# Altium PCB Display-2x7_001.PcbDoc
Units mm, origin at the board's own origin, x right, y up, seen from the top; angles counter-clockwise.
Board outline 37.38 x 73.8 mm, 2 copper layers (Top Layer, Bottom Layer), stack 1.571 mm thick; 20 components, 35 nets, 104 pads, 23 vias.
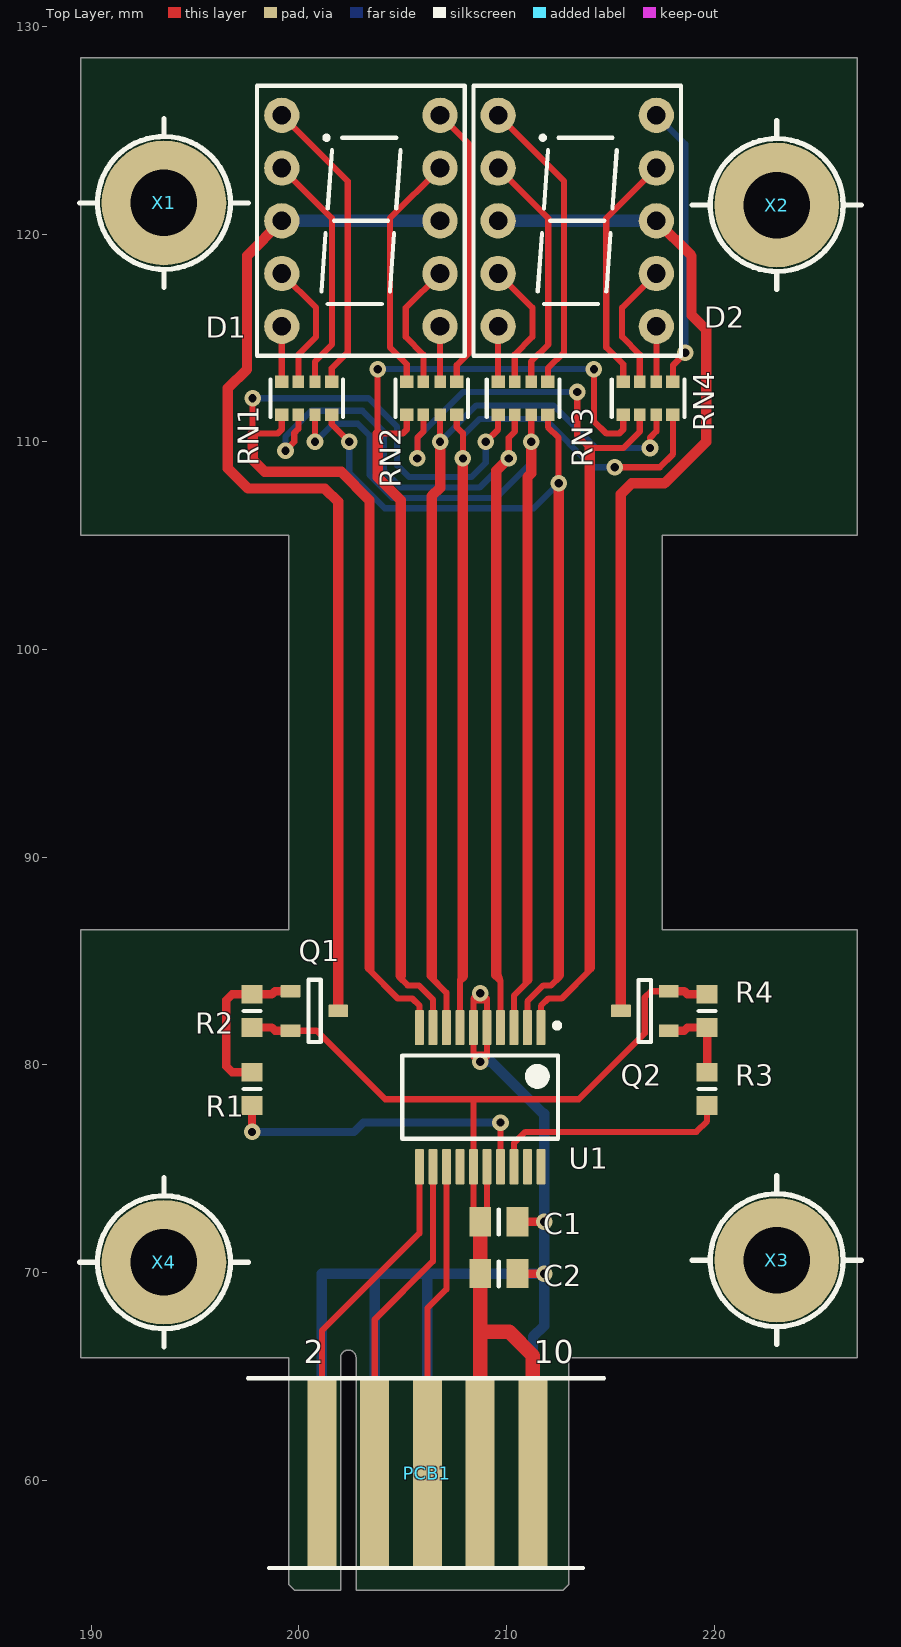
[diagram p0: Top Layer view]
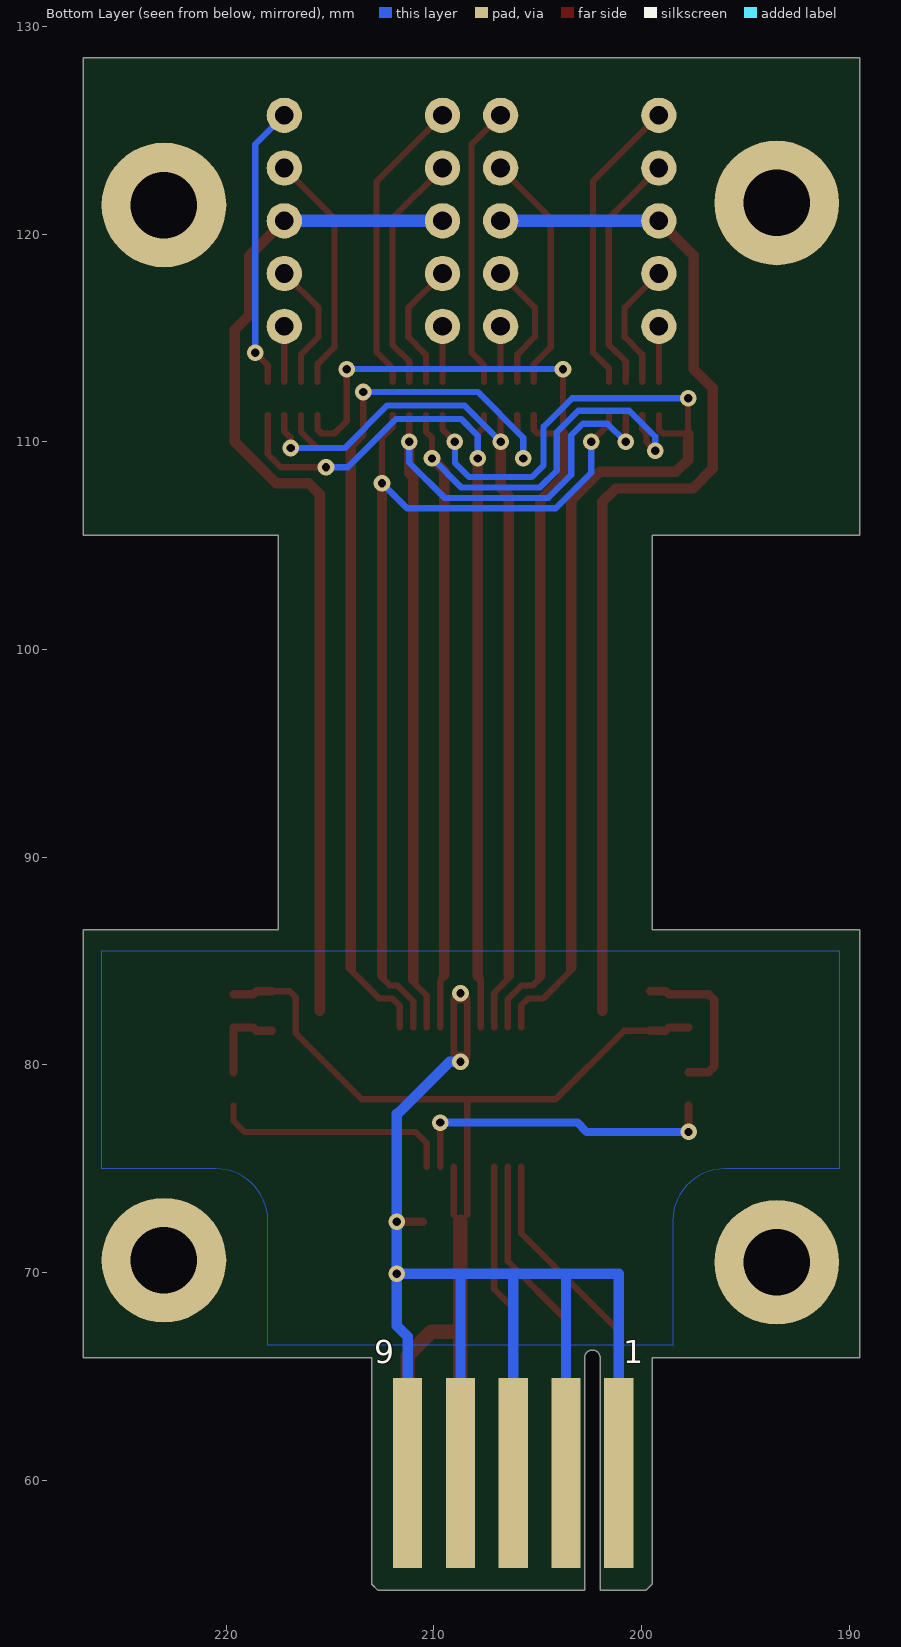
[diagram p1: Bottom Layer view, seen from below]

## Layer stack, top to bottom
Top Solder: solder mask 0.0102, Solder Resist, Dk 3.5
Top Layer: signal copper 0.0356
Flexpart Dielectric: dielectric 0.1, FR-4, Dk 4.2
Core Dielectric: dielectric 1.4, FR-4, Dk 4.2
Bottom Layer: signal copper 0.0356
Bottom Solder: solder mask 0.0102, Solder Resist, Dk 3.5

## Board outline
199.5,55 199.5,65.9 189.5,65.9 189.5,86.5 199.5,86.5 199.5,105.5 189.5,105.5 189.5,128.5 226.88,128.5 226.88,105.5 217.5,105.5 217.5,86.5 226.88,86.5 226.88,65.9 213,65.9 213,55 212.7,54.7 202.75,54.7 202.75,65.9 ccw(c202.375,65.9) 202,65.9 202,54.7 199.8,54.7
board region LED: 199.5,104.5 199.5,105.5 189.5,105.5 189.5,128.5 226.88,128.5 226.88,105.5 217.5,105.5 217.5,104.5
board region IC: 217.5,87.5 217.5,86.5 226.88,86.5 226.88,65.9 213,65.9 213,55 212.7,54.7 202.75,54.7 202.757,65.9 202.728,66.046 202.645,66.17 202.521,66.253 202.375,66.282 202.229,66.253 202.105,66.17 202.022,66.046 201.993,65.9 202,65.9 202,54.7 199.8,54.7 199.5,55 199.5,65.9 189.5,65.9 189.5,86.5 199.5,86.5 199.5,87.5
board region Flex: 217.5,104.5 217.5,87.5 199.5,87.5 199.5,104.5

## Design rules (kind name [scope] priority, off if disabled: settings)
Clearance [All] p1: gap=0.2
MinimumSolderMaskSliver [All] p1: minsoldermaskwidth=0.2
PolygonConnect [All] p1: connectstyle=Relief reliefconductorwidth=0.254 reliefentries=4 polygonreliefangle="90 Angle" airgapwidth=0.254
RoutingVias [All] p1: holewidth=0.5 width=1.27 viastyle="Through Hole" minholewidth=0.4 minwidth=0.8 maxholewidth=0.7 maxwidth=1
SolderMaskExpansion [All] p1: expansion=0.102
Width [All] p1: maxlimit=1 minlimit=0.254 preferedwidth=0.3 minimp=50.000000 maximp=50.000000 favimp=50.000000
28 further rules are at their usual default settings.

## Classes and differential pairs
component class Display-2x7: C1 C2 PCB1 Q1 Q2 R1 R2 R3 R4 U1 X3 X4

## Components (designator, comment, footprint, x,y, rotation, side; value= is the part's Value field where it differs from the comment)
C1 "100n, X7R, 50V" CAPC2012X135N 209.625,72.45 r180 top
C2 "100n, X7R, 50V" CAPC2012X135N 209.625,69.95 r180 top
D1 "SA39-11PBWA" LED_KINGBRIGHT_SA39-11PBWA 202.983,120.64 r180 top
D2 "SA39-11PBWA" LED_KINGBRIGHT_SA39-11PBWA 213.397,120.64 r180 top
PCB1 "PCB_KS_3M_3358" KS_3M_3358 206.185,60.35 r180 top
Q1 "BC856B" SOT95P230X110-3N 200.743,82.6 r0 top
Q2 "BC856B" SOT95P230X110-3N 216.65,82.6 r180 top
R1 "3k3, 5%" RESC1608X55N 197.743,78.85 r270 top
R2 "3k3, 5%" RESC1608X55N 197.743,82.6 r90 top
R3 "3k3, 5%" RESC1608X55N 219.65,78.85 r270 top
R4 "3k3, 5%" RESC1608X55N 219.65,82.6 r270 top
RN1 "4x100R" RESCAV80P160X320X55-8N 200.373,112.093 r90 top
RN2 "4x100R" RESCAV80P160X320X55-8N 206.393,112.093 r90 top
RN3 "4x100R" RESCAV80P160X320X55-8N 210.787,112.093 r90 top
RN4 "4x100R" RESCAV80P160X320X55-8N 216.807,112.093 r90 top
U1 "THC_IC_16C770-IL20" SOP65P780X200-20N 208.725,78.45 r270 top
X1 "Bohrung in LP kein Bauteil" HOLE_3.2_6.0 193.5,121.5 r0 top
X2 "Bohrung in LP kein Bauteil" HOLE_3.2_6.0 223,121.4 r0 top
X3 "Bohrung in LP kein Bauteil" HOLE_3.2_6.0 223,70.6 r0 top
X4 "Bohrung in LP kein Bauteil" HOLE_3.2_6.0 193.5,70.5 r0 top

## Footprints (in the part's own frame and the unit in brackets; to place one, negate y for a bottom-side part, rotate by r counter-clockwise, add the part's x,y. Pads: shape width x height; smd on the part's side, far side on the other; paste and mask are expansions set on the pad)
CAPC2012X135N [mm] "0805"
  rect 1.05x1.4 smd: 1(-0.9,0) 2(0.9,0)
  silkscreen extent 0.01,-0.59 0.01,0.61, body extent -1.1,-0.7 1.1,0.7, height 1.35
HOLE_3.2_6.0 [mm] "Mechanik für M3 Schraube"
  round 6 hole 3.2: 1(0,0)
  silkscreen extent -4.06,-4.06 4.06,4.06
KS_3M_3358 [mm] "Direktsteckverbinder 3000 Serie 10pol RM2,54"
  rect 1.4x9.14 smd far side: 1(5.08,0) 3(2.54,0) 5(0,0) 7(-2.54,0) 9(-5.08,0)
  rect 1.4x9.14 smd: 2(5.08,0) 4(2.54,0) 6(0,0) 8(-2.54,0) 10(-5.08,0)
  silkscreen extent -8.51,-4.57 8.64,4.57, body extent -7,-6.6 6.8,-5, height 0.1
LED_KINGBRIGHT_SA39-11PBWA [mm] "9.9mm (0.39inch) Kingbright Numeric Display"
  round 1.7 hole 0.9: 1(-3.81,5.08) 2(-3.81,2.54) 3(-3.81,0) 4(-3.81,-2.54) 5(-3.81,-5.08) 6(3.81,-5.08) 7(3.81,-2.54) 8(3.81,0) 9(3.81,2.54) 10(3.81,5.08)
  silkscreen extent -5,-6.5 5,6.5, body extent -5,-6.5 5,6.5, height 7
RESC1608X55N [mm] "0603"
  rect 0.9x1 smd: 1(-0.8,0) 2(0.8,0)
  silkscreen extent 0,-0.4 0,0.4, body extent -0.9,-0.5 0.9,0.5, height 0.55
RESCAV80P160X320X55-8N [mm] "WIDERSTAND ARRAY, ARV241 1206"
  rect 0.6x0.65 smd: 1(-0.8,1.2) 4(-0.8,-1.2) 5(0.8,-1.2) 8(0.8,1.2)
  rect 0.6x0.55 smd: 2(-0.8,0.4) 3(-0.8,-0.4) 6(0.8,-0.4) 7(0.8,0.4)
  silkscreen extent -0.9,-1.75 0.9,1.75, body extent -0.6,-1.6 0.6,1.6, height 0.7
SOP65P780X200-20N [mm] "SSOP20, 20-Leads, Body 7,5x5,2mm (max), Pitch 0,65mm, IPC Medium Density"
  rrect20% 1.7x0.42 smd: 1(-3.35,2.925) 2(-3.35,2.275) 3(-3.35,1.625) 4(-3.35,0.975) 5(-3.35,0.325) 6(-3.35,-0.325) 7(-3.35,-0.975) 8(-3.35,-1.625) 9(-3.35,-2.275) 10(-3.35,-2.925) 11(3.35,-2.925) 12(3.35,-2.275) 13(3.35,-1.625) 14(3.35,-0.975) 15(3.35,-0.325) 16(3.35,0.325) 17(3.35,0.975) 18(3.35,1.625) 19(3.35,2.275) 20(3.35,2.925)
  silkscreen extent -3.57,-3.75 2,3.83, body extent -2.65,-3.75 2.65,3.75, height 2
SOT95P230X110-3N [mm]
  rrect10% 0.95x0.6 smd: 1(-1.15,0.95) 3(1.15,0)
  rrect10% 0.95x0.6 smd mask+0.102: 2(-1.15,-0.95)
  silkscreen extent -0.29,-1.5 0.31,1.5, body extent -0.67,-1.5 0.68,1.5, height 1.1

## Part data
C1 C2: library part SMD_CAP_100n0_0805_X7R, "Capacitor 0805 2,0mm x 1,25mm"
D1 D2: library part THC_LED_KINGBRIGHGT_SA39-11PBWA, "9mm 7-Segment, LED, Numeric, Single Digit, Blue KINGBRIGHGT"
PCB1: "Buchsenleiste 3M Serie3000 10pol RM2.54 Card Edge"
Q1 Q2: library part SMD_PNP_BC856B_SOT23, "PNP Transistor 65V 100mA"
R1 R2 R3 R4: library part SMD_RES_003k30_0603_5%, "Resistor 0603 1,55mm x 0,85mm"
RN1 RN2 RN3 RN4: library part SMD_RES_100R00_4x0603_concave_5%, "4X100R Resistor Array 4x0603 concave 5% 63mW"
X1 X2 X3 X4: library part Hole_3.2mm_CU6.0, "Bohrung 3,2mm mit CU"

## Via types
v1: diameter 0.8, hole 0.4, Top Layer to Bottom Layer, 23 vias

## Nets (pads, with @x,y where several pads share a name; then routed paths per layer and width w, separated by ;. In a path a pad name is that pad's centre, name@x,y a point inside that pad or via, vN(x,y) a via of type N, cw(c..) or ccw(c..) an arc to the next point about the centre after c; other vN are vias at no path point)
GND: C1.1 C2.1 PCB1.1 PCB1.3 PCB1.5 PCB1.7 PCB1.9 U1.5 U1.6 | length 84.7
  Top Layer w0.3: 208.4,80.4 U1.6 208.4,83.2 208.725,83.525 209.05,83.2 U1.5 209.05,80.4
  Top Layer w0.4: C2.1 v1(211.8,69.95) ; C1.1 v1(211.8,72.45)
  Bottom Layer w0.5: PCB1.1@201.105,57.85 201.105,69.925 ; 201.105,69.95 v1(211.8,69.95) ; PCB1.3@203.645,57.85 203.645,69.925 ; PCB1.5 206.185,69.925 ; PCB1.7 208.725,69.95 ; v1(208.725,80.15) 209.25,80.15 211.8,77.6 ; PCB1.9 211.265,66.915 211.8,67.45 v1(211.8,69.95) ; 211.8,77.65 v1(211.8,69.95)
  other v1: 208.725,83.45
NetD1_1: D1.1 RN2.6 | length 2.7
  Top Layer w0.3: RN2.6 D1.1
NetD1_2: D1.2 RN2.7 | length 6.2
  Top Layer w0.3: RN2.7 205.993,114.201 205.142,115.052 205.142,116.449 D1.2
NetD1_3: D1.3 D1.8 Q1.3 | length 51.1
  Top Layer w0.5: D1.8 197.5,118.967 197.5,113.5 196.58,112.58 196.58,108.72 197.55,107.75 201.25,107.75 201.893,107.107 Q1.3
  Bottom Layer w0.6: D1.8 D1.3
NetD1_4: D1.4 RN2.8 | length 11.6
  Top Layer w0.3: RN2.8 205.193,113.731 204.38,114.544 204.38,120.767 D1.4
NetD1_5: D1.5 RN2.5 | length 13.7
  Top Layer w0.3: D1.5 208.19,124.323 208.19,114.29 207.593,113.693 RN2.5
NetD1_6: D1.6 RN1.5 | length 14.5
  Top Layer w0.3: D1.6 202.348,122.545 202.348,114.313 201.573,113.538 RN1.5
NetD1_7: D1.7 RN1.6 | length 11.6
  Top Layer w0.3: D1.7 201.586,120.767 201.586,114.683 200.773,113.87 RN1.6
NetD1_9: D1.9 RN1.7 | length 6.2
  Top Layer w0.3: D1.9 200.824,116.449 200.824,115.052 199.973,114.201 RN1.7
NetD1_10: D1.10 RN1.8 | length 2.7
  Top Layer w0.3: RN1.8 D1.10
NetD2_1: D2.1 RN4.6 | length 2.7
  Top Layer w0.3: RN4.6 D2.1
NetD2_2: D2.2 RN4.7 | length 6.2
  Top Layer w0.3: RN4.7 216.407,114.201 215.556,115.052 215.556,116.449 D2.2
NetD2_3: D2.3 D2.8 Q2.3 | length 49.3
  Top Layer w0.5: Q2.3 215.5,107.475 216.025,108 217.6,108 219.6,110 219.6,115.4 218.9,116.1 218.9,118.947 D2.3
  Bottom Layer w0.6: D2.8 D2.3
NetD2_4: D2.4 RN4.8 | length 11.6
  Top Layer w0.3: RN4.8 215.607,113.731 214.794,114.544 214.794,120.767 D2.4
NetD2_5: D2.5 RN4.5 | length 13.7
  Top Layer w0.3: RN4.5 218.007,113.693 v1(218.604,114.29)
  Bottom Layer w0.3: D2.5 218.604,124.323 v1(218.604,114.29)
NetD2_6: D2.6 RN3.5 | length 14.5
  Top Layer w0.3: D2.6 212.762,122.545 212.762,114.313 211.987,113.538 RN3.5
NetD2_7: D2.7 RN3.6 | length 11.6
  Top Layer w0.3: D2.7 212,120.767 212,114.683 211.187,113.87 RN3.6
NetD2_9: D2.9 RN3.7 | length 6.2
  Top Layer w0.3: D2.9 211.238,116.449 211.238,115.052 210.387,114.201 RN3.7
NetD2_10: D2.10 RN3.8 | length 2.7
  Top Layer w0.3: RN3.8 D2.10
NetPCB1_2: PCB1.2 U1.11 | length 16.7
  Top Layer w0.3: PCB1.2 201.105,67.205 205.8,71.9 U1.11
NetPCB1_4: PCB1.4 U1.12 | length 15.9
  Top Layer w0.3: PCB1.4 203.645,67.745 206.45,70.55 U1.12
NetPCB1_6: PCB1.6 U1.13 | length 15.1
  Top Layer w0.3: PCB1.6 206.185,68.285 207.1,69.2 U1.13
NetQ1_1: Q1.1 R1.1 R2.2 | length 7.8
  Top Layer w0.4: R1.1 196.775,79.65 196.5,79.925 196.5,83.125 196.775,83.4 R2.2 198.693,83.4 198.843,83.55 Q1.1
NetQ2_1: Q2.1 R3.1 R4.2 | length 4.1
  Top Layer w0.4: Q2.1 218.55,81.65 218.7,81.8 R4.2 R3.1
NetR1_2: R1.2 U1.17 | length 15.5
  Top Layer w0.3: U1.17 v1(209.7,77.225)
  Top Layer w0.4: v1(197.743,76.775) R1.2
  Bottom Layer w0.4: v1(197.743,76.775) 202.65,76.775 203.1,77.225 v1(209.7,77.225)
NetR3_2: R3.2 U1.18 | length 11.6
  Top Layer w0.3: U1.18 210.35,76.225 210.9,76.775 219.125,76.775 219.65,77.3 R3.2
NetRN1_1: RN1.1 RN3.1 U1.10 | length 55.1
  Top Layer w0.3: v1(197.766,112.1) 197.766,110.4 198.98,110.4 199.173,110.593 RN1.1 ; 203.325,84.625 204.75,83.2 205.463,83.2 205.8,82.863 U1.10 ; v1(208.994,110) 209.587,110.593 RN3.1
  Top Layer w0.5: 197.766,110.4 197.766,109.134 198.35,108.55 202.027,108.55 203.393,107.183 203.393,84.7
  Bottom Layer w0.3: v1(197.766,112.1) 203.35,112.1 204.725,110.725 204.725,108.875 205.3,108.3 208.3,108.3 208.994,108.994 v1(208.994,110)
NetRN1_2: RN1.2 RN3.2 U1.4 | length 47.1
  Top Layer w0.3: v1(199.35,109.575) 199.775,110 199.775,110.425 199.973,110.623 RN1.2 ; 209.5,84.35 209.5,84.225 209.7,84.025 U1.4 ; v1(210.094,109.2) 210.094,110.2 210.387,110.493 RN3.2
  Top Layer w0.5: 209.5,84.35 209.5,108.606 v1(210.094,109.2)
  Bottom Layer w0.3: v1(199.35,109.575) 199.35,110.25 200.6,111.5 203.056,111.5 204.093,110.463 204.093,108.607 204.9,107.8 208.694,107.8 v1(210.094,109.2)
NetRN1_3: RN1.3 RN3.3 U1.3 | length 46.2
  Top Layer w0.3: v1(200.773,110) RN1.3 ; U1.3 210.35,83.329 211.068,84.047 ; v1(211.187,110) RN3.3
  Top Layer w0.5: 211,84.122 211,108.3 211.187,108.487 v1(211.187,110)
  Bottom Layer w0.3: v1(200.773,110) 201.648,110.875 202.831,110.875 203.393,110.313 203.393,108.407 204.5,107.3 209.493,107.3 211.187,108.994 v1(211.187,110)
NetRN1_4: RN1.4 RN3.4 U1.2 | length 44.6
  Top Layer w0.3: RN1.4 201.573,110.852 v1(202.425,110) ; U1.2 211,83.057 211.769,83.826 212.135,83.826 212.568,84.259 ; RN3.4 211.987,110.707 212.5,110.194 v1(212.5,108)
  Top Layer w0.5: 212.5,84.334 v1(212.5,108)
  Bottom Layer w0.3: v1(202.425,110) 202.425,108.51 204.135,106.8 211.3,106.8 v1@212.287,107.787
NetRN2_1: RN2.1 RN4.1 U1.9 | length 50.6
  Top Layer w0.3: v1(203.786,113.5) 203.786,110.4 205,110.4 205.193,110.593 RN2.1 ; 204.825,84.234 205.233,83.826 205.777,83.826 206.45,83.153 U1.9 ; v1(214.2,113.5) 214.2,111 214.8,110.4 215.414,110.4 215.607,110.593 RN4.1
  Top Layer w0.5: 203.786,110.4 203.786,108.286 204.893,107.179 204.893,84.309
  Bottom Layer w0.3: v1(203.786,113.5) v1(214.2,113.5)
NetRN2_2: RN2.2 RN4.2 U1.1 | length 47.5
  Top Layer w0.3: v1(205.7,109.2) 205.7,110.2 205.993,110.493 RN2.2 ; U1.1 211.65,82.841 212.009,83.2 212.643,83.2 214.068,84.625 ; v1(213.4,112.4) 213.4,110.3 214,109.7 215.614,109.7 216.407,110.493 RN4.2
  Top Layer w0.5: 214,84.7 214,109.7
  Bottom Layer w0.3: v1(205.7,109.2) 205.7,110.2 207.9,112.4 v1(213.4,112.4)
NetRN2_3: RN2.3 RN4.3 U1.8 | length 43.3
  Top Layer w0.3: 206.325,84.259 207.1,83.484 U1.8 ; v1(206.793,110) RN2.3 ; v1(216.9,109.7) 216.9,110.2 217.207,110.507 RN4.3
  Top Layer w0.5: 206.393,84.309 206.393,107.393 206.793,107.793 v1(206.793,110)
  Bottom Layer w0.3: v1(206.793,110) 208.543,111.75 212.25,111.75 214.3,109.7 v1(216.9,109.7)
NetRN2_4: RN2.4 RN4.4 U1.7 | length 44.3
  Top Layer w0.3: RN2.4 207.593,110.707 207.893,110.407 v1(207.893,109.2) ; U1.7 207.75,84 207.975,84.225 ; v1(215.2,108.775) 217.375,108.775 218.007,109.407 RN4.4
  Top Layer w0.5: 207.893,84.3 v1(207.893,109.2)
  Bottom Layer w0.3: v1(207.893,109.2) 207.893,110.293 208.7,111.1 211.825,111.1 214.15,108.775 v1(215.2,108.775)
VCC: C1.2 C2.2 PCB1.8 PCB1.10 Q1.2 Q2.2 R2.1 R4.1 U1.15 U1.16 | length 55.2
  Top Layer w0.3: Q1.2 200.85,81.65 204.15,78.35 209.05,78.35 213.475,78.35 216.65,81.525 216.65,83.25 216.95,83.55 Q2.2 ; C1.2@208.4,72.775 U1.15 208.4,78.35 ; C1.2@209.05,72.775 U1.16
  Top Layer w0.4: R2.1 198.693,81.8 198.843,81.65 Q1.2 ; Q2.2 218.55,83.55 218.7,83.4 R4.1
  Top Layer w0.7: PCB1.8 C1.2 ; 208.725,67.15 210.125,67.15 211.265,66.01 PCB1.10
pads on no net: U1.14 U1.19 U1.20 X1.1 X2.1 X3.1 X4.1

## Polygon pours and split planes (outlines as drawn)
GND on Bottom Layer "Bottom Layer-No Net" (solid, remove dead copper, pour order 4): 190.5,85.5 190.5,75 196,75 cw(c196,72.5) 198.5,72.5 198.5,71.5 198.5,66.5 218,66.5 218,72.5 cw(c220.5,72.5) 220.5,75 226,75 226,81 226,85.5 190.5,85.5

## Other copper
Top Layer:
  region net GND: 209.05,80.65 208.4,80.65 208.4,80.175 209.05,80.175
  rectangle net GND: 208.4,82.95 209.05,83.425
  region net NetRN1_4: 212.493,84.553 212.252,84.553 212.252,84.034 212.493,84.034
  rectangle net NetRN2_3: 206.4,84.034 206.641,84.553
  rectangle net NetRN2_1: 204.9,84.009 205.141,84.527
  region net NetRN1_3: 210.993,84.34 210.752,84.34 210.752,83.822 210.993,83.822
  region net NetRN2_2: 213.993,84.918 213.752,84.918 213.752,84.4 213.993,84.4
  rectangle net NetRN1_1: 203.4,84.4 203.641,84.918
  region net NetRN1_2: 209.598,84 209.84,84.064 209.678,84.67 209.436,84.605
  region net NetRN2_4: 207.977,84.524 207.652,84.552 207.604,84.013 207.93,83.984

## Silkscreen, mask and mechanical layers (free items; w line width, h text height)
Mechanical 1:
  lines w0.254: 189.5,66 189.5,86.5 199.5,86.5 199.5,105.5 189.5,105.5 189.5,128.5 226.88,128.5 226.88,105.5 217.5,105.5 217.5,86.5 226.88,86.5 226.88,66 213,66 213,55.1 212.7,54.8 202.75,54.8 202.75,66 ccw(c202.375,66) 202,66 202,54.8 199.8,54.8 199.5,55.1 199.5,66 189.5,66
Mechanical 2:
  drawing of 557 lines, arcs and shapes, not listed
  text "Layer" at 111.5,179.5 h1.52
  text "Name" at 121.912,179.5 h1.52
  text "Material" at 152.383,179.5 h1.52
  text "Thickness" at 174.221,179.5 h1.52
  text "Constant" at 190.727,179.5 h1.52
  text "Board Layer Stack 1" at 205.201,179.5 h1.52
  text "SemiFlex" at 236.434,179.5 h1.52
  text "1" at 111.5,176.452 h1.52
  text "Top Paste" at 121.912,176.452 h1.52
  text "2" at 111.5,173.404 h1.52
  text "Top Overlay" at 121.912,173.404 h1.52
  text "3" at 111.5,170.356 h1.52
  text "Top Solder" at 121.912,170.356 h1.52
  text "Solder Resist" at 152.383,170.356 h1.52
  text "0,010mm" at 174.221,170.356 h1.52
  text "3,5" at 190.727,170.356 h1.52
  text "4" at 111.5,167.308 h1.52
  text "Top Layer" at 121.912,167.308 h1.52
  text "Copper" at 152.383,167.308 h1.52
  text "0,036mm" at 174.221,167.308 h1.52
  text "5" at 111.5,164.26 h1.52
  text "Flexpart Dielectric" at 121.912,164.26 h1.52
  text "FR-4" at 152.383,164.26 h1.52
  text "0,100mm" at 174.221,164.26 h1.52
  text "4,2" at 190.727,164.26 h1.52
  text "6" at 111.5,161.212 h1.52
  text "Core Dielectric" at 121.912,161.212 h1.52
  text "FR-4" at 152.383,161.212 h1.52
  text "1,400mm" at 174.221,161.212 h1.52
  text "4,2" at 190.727,161.212 h1.52
  text "7" at 111.5,158.164 h1.52
  text "Bottom Layer" at 121.912,158.164 h1.52
  text "Copper" at 152.383,158.164 h1.52
  text "0,036mm" at 174.221,158.164 h1.52
  text "8" at 111.5,155.116 h1.52
  text "Bottom Solder" at 121.912,155.116 h1.52
  text "Solder Resist" at 152.383,155.116 h1.52
  text "0,010mm" at 174.221,155.116 h1.52
  text "3,5" at 190.727,155.116 h1.52
  text "9" at 111.5,152.068 h1.52
  text "Bottom Overlay" at 121.912,152.068 h1.52
  text "10" at 111.5,149.02 h1.52
  text "Bottom Paste" at 121.912,149.02 h1.52
Drill Drawing:
  circle w0.025: c156.34,29.158 r0.635
  lines w0.025: 155.705,24.713 156.975,24.713 156.975,25.983 155.705,25.983 155.705,24.713 ; 155.705,33.603 156.975,33.603 156.34,32.333 155.705,33.603
  lines w0.381: 153.974,23.57 252.5,23.57 ; 153.974,35 252.5,35 ; 167.966,19.76 167.966,38.81 ; 185.691,19.76 185.691,38.81 ; 219.869,19.76 219.869,38.81 ; 232.718,19.76 232.718,38.81 ; 153.974,19.76 252.5,19.76 252.5,38.81 153.974,38.81 153.974,19.76
  text "Symbol" at 156.26,36.143 h1.83
  text "Hit Count" at 169.109,36.143 h1.83
  text "Finished Hole Size" at 186.834,36.143 h1.83
  text "Plated" at 221.012,36.143 h1.83
  text "Hole Type" at 233.861,36.143 h1.83
  text "4" at 169.109,32.333 h1.52
  text "3,200mm (125,98mil)" at 186.834,32.333 h1.52
  text "PTH" at 221.012,32.333 h1.52
  text "Round" at 233.861,32.333 h1.52
  text "20" at 169.109,28.523 h1.52
  text "0,900mm (35,43mil)" at 186.834,28.523 h1.52
  text "PTH" at 221.012,28.523 h1.52
  text "Round" at 233.861,28.523 h1.52
  text "23" at 169.109,24.713 h1.52
  text "0,400mm (15,75mil)" at 186.834,24.713 h1.52
  text "PTH" at 221.012,24.713 h1.52
  text "Round" at 233.861,24.713 h1.52
  text "47 Total" at 169.109,20.903 h1.52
